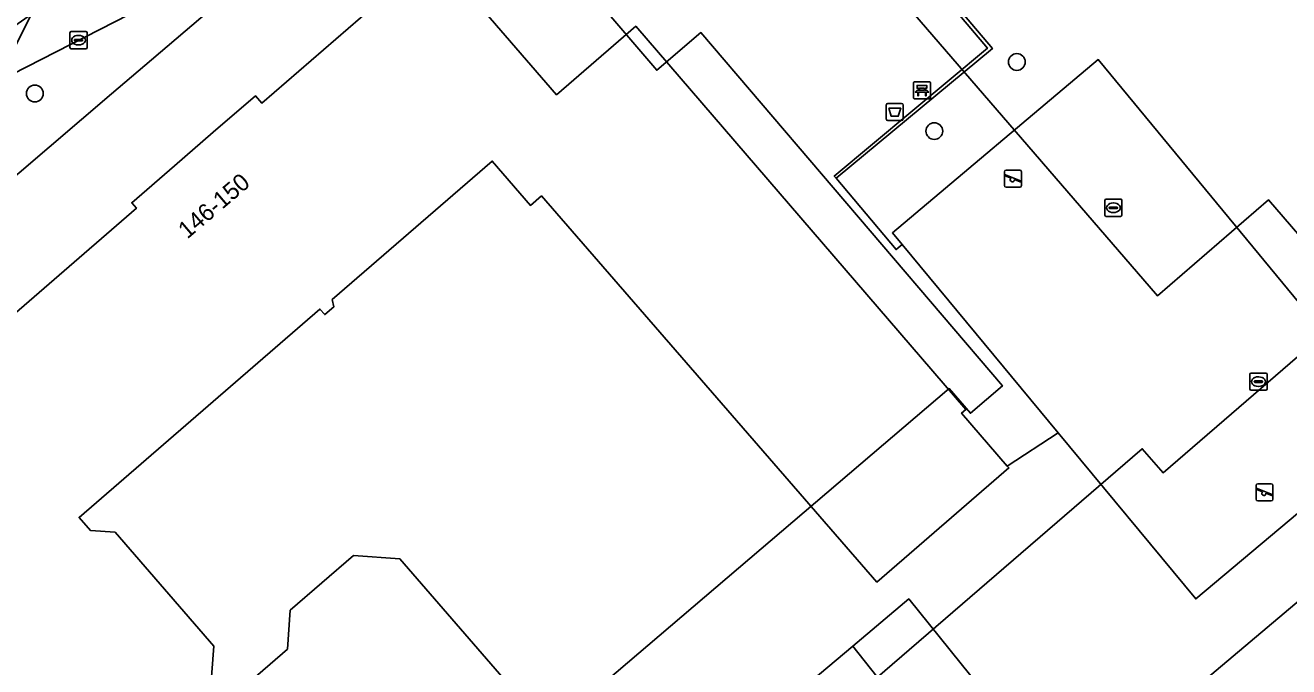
# Model space of a CAD drawing. Extents: x 162172 to 163187, y 382874 to 383685.
# Drawn here: x 162560 to 162633.7, y 383391.8 to 383429.2 of the extents above; entities that cross this region are included whole.
import ezdxf

# ---------------------------------------------------------------- set-up
doc = ezdxf.new("R2010")
doc.units = 0
for name, color, linetype in [('IMGEO_Afvalbak', 7, 'Continuous'), ('IMGEO_Bank', 7, 'Continuous'), ('IMGEO_Boom', 7, 'Continuous'), ('IMGEO_Erf', 7, 'Continuous'), ('IMGEO_Fietspad_gesloten', 7, 'Continuous'), ('IMGEO_Groenvoorziening', 7, 'Continuous'), ('IMGEO_Hek', 7, 'Continuous'), ('IMGEO_Kolk', 7, 'Continuous'), ('IMGEO_Muur', 7, 'Continuous'), ('IMGEO_Pand', 7, 'Continuous'), ('IMGEO_Pand_nummerreeks', 7, 'Continuous'), ('IMGEO_Pand_vergunning_verleend', 7, 'Continuous'), ('IMGEO_Parkeervlak_open', 7, 'Continuous'), ('IMGEO_Rijbaan_lokaal_gesloten', 7, 'Continuous'), ('IMGEO_Rijbaan_lokaal_open', 7, 'Continuous'), ('IMGEO_Speelvoorziening', 7, 'Continuous'), ('IMGEO_Terreindeel_gesloten', 7, 'Continuous'), ('IMGEO_Voetpad_open', 7, 'Continuous')]:
    doc.layers.add(name, color=color, linetype=linetype)

msp = doc.modelspace()

# ---------------------------------------------------------------- linework, layer by layer
at = {"layer": 'IMGEO_Afvalbak'}
for p, q in [((162610.314, 383424.681), (162611.104, 383424.681)), ((162611.104, 383424.681), (162610.314, 383424.681)), ((162610.214, 383423.781), (162610.214, 383424.581)), ((162610.214, 383424.581), (162610.214, 383423.781)), ((162611.204, 383424.581), (162611.204, 383423.781)), ((162611.204, 383423.781), (162611.204, 383424.581)), ((162611.104, 383423.681), (162610.314, 383423.681)), ((162610.314, 383423.681), (162611.104, 383423.681))]:
    msp.add_line(p, q, dxfattribs=at)
msp.add_lwpolyline([(162610.357, 383424.395), (162611.061, 383424.395), (162610.912, 383423.925), (162610.506, 383423.925), (162610.357, 383424.395)], dxfattribs=at)
for centre, start, end in [((162610.314, 383424.581), 90, 180), ((162610.314, 383424.581), 90, 180), ((162611.104, 383424.581), 0, 90), ((162611.104, 383424.581), 360, 90), ((162610.314, 383423.781), 180, 270), ((162610.314, 383423.781), 180, 270), ((162611.104, 383423.781), 270, 0), ((162611.104, 383423.781), 270, 0)]:
    msp.add_arc(centre, 0.1, start, end, dxfattribs=at)
at = {"layer": 'IMGEO_Bank'}
for p, q in [((162611.795, 383425.019), (162611.795, 383425.86)), ((162611.795, 383425.86), (162611.795, 383425.019)), ((162611.87, 383425.944), (162612.711, 383425.944)), ((162612.711, 383425.944), (162611.87, 383425.944)), ((162612.104, 383425.45), (162612.104, 383425.556)), ((162612.148, 383425.556), (162612.148, 383425.45)), ((162612.436, 383425.562), (162612.154, 383425.562)), ((162612.154, 383425.444), (162612.436, 383425.444)), ((162612.442, 383425.45), (162612.442, 383425.556)), ((162612.486, 383425.556), (162612.486, 383425.45)), ((162612.795, 383425.869), (162612.795, 383425.028)), ((162612.795, 383425.028), (162612.795, 383425.869)), ((162612.72, 383424.944), (162611.879, 383424.944)), ((162611.879, 383424.944), (162612.72, 383424.944)), ((162612.492, 383425.342), (162612.099, 383425.342))]:
    msp.add_line(p, q, dxfattribs=at)
for points in [[(162612.042, 383425.342), (162611.9, 383425.342), (162612.012, 383425.444), (162612.098, 383425.444)], [(162612.098, 383425.562), (162612.012, 383425.562), (162612.012, 383425.723), (162612.575, 383425.723), (162612.575, 383425.562), (162612.492, 383425.562)], [(162612.492, 383425.444), (162612.575, 383425.444), (162612.687, 383425.342), (162612.548, 383425.342)], [(162612.092, 383425.335), (162612.092, 383425.128), (162612.049, 383425.128), (162612.049, 383425.335)], [(162612.542, 383425.335), (162612.542, 383425.128), (162612.498, 383425.128), (162612.498, 383425.335)]]:
    msp.add_lwpolyline(points, dxfattribs=at)
for centre, radius, start, end in [((162611.873, 383425.866), 0.0779, 92.4484, 184.28452), ((162611.873, 383425.866), 0.0779, 92.4484, 184.28452), ((162612.097, 383425.555), 0.00671, 2.89567, 87.10433), ((162612.097, 383425.451), 0.00671, 272.89567, 357.10433), ((162612.154, 383425.555), 0.00671, 92.89567, 177.10433), ((162612.154, 383425.451), 0.00671, 182.89567, 267.10433), ((162612.436, 383425.555), 0.00671, 2.89567, 87.10433), ((162612.436, 383425.451), 0.00671, 272.89567, 357.10433), ((162612.493, 383425.555), 0.00671, 92.89567, 177.10433), ((162612.493, 383425.451), 0.00671, 182.89567, 267.10433), ((162612.717, 383425.866), 0.0779, 2.4484, 94.28452), ((162612.717, 383425.866), 0.0779, 2.4484, 94.28452), ((162611.873, 383425.022), 0.0779, 182.4484, 274.28452), ((162611.873, 383425.022), 0.0779, 182.4484, 274.28452), ((162612.042, 383425.335), 0.00671, 2.89567, 87.10433), ((162612.099, 383425.335), 0.00671, 92.89567, 177.10433), ((162612.491, 383425.335), 0.00671, 2.89567, 87.10433), ((162612.548, 383425.335), 0.00671, 92.89567, 177.10433), ((162612.717, 383425.022), 0.0779, 272.4484, 4.28452), ((162612.717, 383425.022), 0.0779, 272.4484, 4.28452)]:
    msp.add_arc(centre, radius, start, end, dxfattribs=at)
at = {"layer": 'IMGEO_Boom'}
for centre in [(162617.822, 383427.095), (162560.596, 383425.254), (162613.013, 383423.066)]:
    msp.add_circle(centre, 0.489, dxfattribs=at)
at = {"layer": 'IMGEO_Erf'}
for points in [[(162596.138, 383451.763), (162616.404, 383427.879), (162607.288, 383420.314), (162610.782, 383416.159), (162611.135, 383416.447), (162610.574, 383417.124), (162622.57, 383427.234), (162640.23, 383405.844), (162628.253, 383395.788), (162620.223, 383405.479), (162617.266, 383403.538), (162617.36, 383403.43), (162609.664, 383396.767), (162590.117, 383419.288), (162589.479, 383418.736), (162587.247, 383421.314), (162577.927, 383413.245), (162578.01, 383412.814), (162577.488, 383412.362), (162577.207, 383412.687), (162563.178, 383400.543), (162563.838, 383399.781), (162565.274, 383399.678), (162571.023, 383393.038), (162570.82, 383390.218)], [(162620.769, 383384.316), (162642.074, 383402.265)], [(162572.149, 383390.123), (162575.314, 383392.863), (162575.476, 383395.124), (162579.165, 383398.318), (162581.875, 383398.123), (162594.112, 383383.992)], [(162603.302, 383388.849), (162608.27, 383393.04), (162611.524, 383395.786), (162618.111, 383387.614)]]:
    msp.add_lwpolyline(points, dxfattribs=at)
at = {"layer": 'IMGEO_Fietspad_gesloten'}
msp.add_lwpolyline([(162560.399, 383429.887), (162558.403, 383425.945), (162567.8, 383430.751)], dxfattribs=at)
at = {"layer": 'IMGEO_Groenvoorziening'}
msp.add_lwpolyline([(162552.395, 383414.415), (162556.323, 383409.744), (162566.514, 383418.568), (162566.243, 383418.882), (162568.73, 383421.035), (162570.997, 383422.998), (162573.45, 383425.122), (162573.816, 383424.699), (162583.879, 383433.412), (162579.936, 383437.929), (162567.388, 383427.216), (162565.072, 383425.239)], close=True, dxfattribs=at)
at = {"layer": 'IMGEO_Hek'}
for points in [[(162611.135, 383416.447), (162610.574, 383417.124), (162622.57, 383427.234), (162640.23, 383405.844), (162628.253, 383395.788)], [(162620.223, 383405.479), (162611.135, 383416.447)], [(162617.266, 383403.538), (162620.223, 383405.479)], [(162628.253, 383395.788), (162620.223, 383405.479)]]:
    msp.add_lwpolyline(points, dxfattribs=at)
at = {"layer": 'IMGEO_Kolk'}
for p, q in [((162562.642, 383427.941), (162562.642, 383428.793)), ((162562.717, 383428.867), (162563.569, 383428.867)), ((162562.901, 383428.361), (162562.901, 383428.373)), ((162562.944, 383428.41), (162563.342, 383428.41)), ((162563.13, 383428.647), (162563.155, 383428.647)), ((162563.385, 383428.373), (162563.385, 383428.361)), ((162563.643, 383428.793), (162563.643, 383427.941)), ((162563.569, 383427.867), (162562.717, 383427.867)), ((162563.339, 383428.324), (162562.941, 383428.324)), ((162563.153, 383428.087), (162563.128, 383428.087)), ((162622.95, 383418.167), (162622.95, 383419.019)), ((162623.025, 383419.093), (162623.877, 383419.093)), ((162623.438, 383418.873), (162623.463, 383418.873)), ((162623.951, 383419.019), (162623.951, 383418.167)), ((162623.877, 383418.093), (162623.025, 383418.093)), ((162623.209, 383418.587), (162623.209, 383418.599)), ((162623.647, 383418.55), (162623.249, 383418.55)), ((162623.252, 383418.636), (162623.65, 383418.636)), ((162623.461, 383418.313), (162623.436, 383418.313)), ((162623.693, 383418.599), (162623.693, 383418.587)), ((162631.404, 383408.031), (162631.404, 383408.883)), ((162631.479, 383408.957), (162632.331, 383408.957)), ((162631.663, 383408.451), (162631.663, 383408.463)), ((162631.706, 383408.5), (162632.104, 383408.5)), ((162631.892, 383408.737), (162631.917, 383408.737)), ((162632.147, 383408.463), (162632.147, 383408.451)), ((162632.405, 383408.883), (162632.405, 383408.031)), ((162632.331, 383407.957), (162631.479, 383407.957)), ((162632.101, 383408.414), (162631.703, 383408.414)), ((162631.915, 383408.177), (162631.89, 383408.177))]:
    msp.add_line(p, q, dxfattribs=at)
for points in [[(162562.642, 383427.941), (162562.642, 383428.793)], [(162562.717, 383428.867), (162563.569, 383428.867)], [(162563.643, 383428.793), (162563.643, 383427.941)], [(162563.569, 383427.867), (162562.717, 383427.867)], [(162622.95, 383418.167), (162622.95, 383419.019)], [(162623.025, 383419.093), (162623.877, 383419.093)], [(162623.951, 383419.019), (162623.951, 383418.167)], [(162623.877, 383418.093), (162623.025, 383418.093)], [(162631.404, 383408.031), (162631.404, 383408.883)], [(162631.479, 383408.957), (162632.331, 383408.957)], [(162632.405, 383408.883), (162632.405, 383408.031)], [(162632.331, 383407.957), (162631.479, 383407.957)]]:
    msp.add_lwpolyline(points, dxfattribs=at)
for centre, radius, start, end in [((162562.719, 383428.791), 0.0765, 91.55205, 178.44795), ((162562.719, 383428.791), 0.0765, 91.55205, 178.44795), ((162562.941, 383428.37), 0.0403, 85.87752, 175.75265), ((162562.938, 383428.36), 0.0366, 178.93798, 274.71019), ((162563.342, 383428.367), 0.043, 264.86636, 352.45326), ((162563.346, 383428.372), 0.0386, 1.73085, 96.63898), ((162563.567, 383428.791), 0.0765, 1.55205, 88.44795), ((162563.567, 383428.791), 0.0765, 1.55205, 88.44795), ((162562.719, 383427.943), 0.0765, 181.55205, 268.44795), ((162562.719, 383427.943), 0.0765, 181.55205, 268.44795), ((162563.567, 383427.943), 0.0765, 271.55205, 358.44795), ((162563.567, 383427.943), 0.0765, 271.55205, 358.44795), ((162623.027, 383419.017), 0.0765, 91.55205, 178.44795), ((162623.027, 383419.017), 0.0765, 91.55205, 178.44795), ((162623.875, 383419.017), 0.0765, 1.55205, 88.44795), ((162623.875, 383419.017), 0.0765, 1.55205, 88.44795), ((162623.027, 383418.169), 0.0765, 181.55205, 268.44795), ((162623.027, 383418.169), 0.0765, 181.55205, 268.44795), ((162623.249, 383418.596), 0.0403, 85.87752, 175.75265), ((162623.246, 383418.586), 0.0366, 178.93798, 274.71019), ((162623.65, 383418.593), 0.043, 264.86636, 352.45326), ((162623.654, 383418.598), 0.0386, 1.73085, 96.63898), ((162623.875, 383418.169), 0.0765, 271.55205, 358.44795), ((162623.875, 383418.169), 0.0765, 271.55205, 358.44795), ((162631.481, 383408.881), 0.0765, 91.55205, 178.44795), ((162631.481, 383408.881), 0.0765, 91.55205, 178.44795), ((162631.703, 383408.46), 0.0403, 85.87752, 175.75265), ((162632.108, 383408.462), 0.0386, 1.73085, 96.63898), ((162632.329, 383408.881), 0.0765, 1.55205, 88.44795), ((162632.329, 383408.881), 0.0765, 1.55205, 88.44795), ((162631.481, 383408.033), 0.0765, 181.55205, 268.44795), ((162631.481, 383408.033), 0.0765, 181.55205, 268.44795), ((162631.7, 383408.45), 0.0366, 178.93798, 274.71019), ((162632.104, 383408.457), 0.043, 264.86636, 352.45326), ((162632.329, 383408.033), 0.0765, 271.55205, 358.44795), ((162632.329, 383408.033), 0.0765, 271.55205, 358.44795)]:
    msp.add_arc(centre, radius, start, end, dxfattribs=at)
for centre, major_axis, ratio, start_param, end_param in [((162563.129, 383428.367), (-0.387, 0.002), 0.722429, 4.712389, 7.853982), ((162563.154, 383428.367), (-0.39, 0.002), 0.717154, 1.570796, 4.712389), ((162623.437, 383418.593), (-0.387, 0.002), 0.722429, 4.712389, 7.853982), ((162623.462, 383418.593), (-0.39, 0.002), 0.717154, 1.570796, 4.712389), ((162631.891, 383408.457), (-0.387, 0.002), 0.722429, 4.712389, 7.853982), ((162631.916, 383408.457), (-0.39, 0.002), 0.717154, 1.570796, 4.712389)]:
    msp.add_ellipse(centre, major_axis=major_axis, ratio=ratio, start_param=start_param, end_param=end_param, dxfattribs=at)
at = {"layer": 'IMGEO_Muur'}
msp.add_lwpolyline([(162596.004, 383451.649), (162616.112, 383427.895), (162607.178, 383420.445), (162607.288, 383420.314), (162616.404, 383427.879), (162596.138, 383451.763)], close=True, dxfattribs=at)
at = {"layer": 'IMGEO_Pand'}
for points in [[(162570.82, 383390.218), (162571.023, 383393.038), (162565.274, 383399.678), (162563.838, 383399.781), (162563.178, 383400.543), (162577.207, 383412.687), (162577.488, 383412.362), (162578.01, 383412.814), (162577.927, 383413.245), (162587.247, 383421.314), (162589.479, 383418.736), (162590.117, 383419.288), (162609.664, 383396.767), (162617.36, 383403.43), (162617.266, 383403.538), (162614.599, 383406.619), (162614.841, 383406.828), (162595.611, 383429.18), (162591, 383425.186), (162583.879, 383433.412), (162573.816, 383424.699), (162573.45, 383425.122), (162570.997, 383422.998), (162568.73, 383421.035), (162566.243, 383418.882), (162566.514, 383418.568), (162556.323, 383409.744)], [(162594.112, 383383.992), (162581.875, 383398.123), (162579.165, 383398.318), (162575.476, 383395.124), (162575.314, 383392.863), (162572.149, 383390.123)]]:
    msp.add_lwpolyline(points, dxfattribs=at)
at = {"layer": 'IMGEO_Pand_vergunning_verleend'}
msp.add_lwpolyline([(162590.329, 383439.322), (162598.084, 383445.937), (162594.444, 383450.204), (162599.136, 383454.207), (162611.229, 383442.452), (162605.368, 383437.395), (162626.018, 383413.461), (162632.496, 383419.049), (162637.734, 383412.977), (162626.341, 383403.148), (162625.134, 383404.547), (162599.092, 383382.079), (162592.496, 383389.812), (162613.886, 383408.056), (162615.116, 383406.614), (162616.983, 383408.207), (162599.41, 383428.809), (162596.839, 383426.615), (162591.037, 383433.417), (162593.543, 383435.555)], close=True, dxfattribs=at)
at = {"layer": 'IMGEO_Parkeervlak_open'}
for points in [[(162617.266, 383403.538), (162620.223, 383405.479), (162611.135, 383416.447), (162610.782, 383416.159), (162607.288, 383420.314), (162607.178, 383420.445), (162616.112, 383427.895), (162596.004, 383451.649), (162589.352, 383445.969), (162587.439, 383444.336), (162582.374, 383440.011), (162579.936, 383437.929), (162583.879, 383433.412), (162591, 383425.186), (162595.611, 383429.18), (162614.841, 383406.828), (162614.599, 383406.619)], [(162643.158, 383401.027), (162642.074, 383402.265), (162620.769, 383384.316), (162618.111, 383387.614), (162611.524, 383395.786), (162608.27, 383393.04), (162617.405, 383381.482), (162619.242, 383379.303), (162622.604, 383382.138), (162623.703, 383380.833), (162643.694, 383397.868), (162651.152, 383404.224), (162651.495, 383404.516), (162649.554, 383406.289)]]:
    msp.add_lwpolyline(points, close=True, dxfattribs=at)
at = {"layer": 'IMGEO_Rijbaan_lokaal_gesloten'}
msp.add_lwpolyline([(162558.23, 383425.842), (162558.403, 383425.945), (162560.399, 383429.887), (162554.504, 383425.759), (162531.546, 383406.134), (162533.265, 383404.182), (162534.219, 383405.065), (162543.666, 383413.944), (162547.279, 383417.243), (162548.765, 383418.485), (162551.849, 383421.163)], dxfattribs=at)
at = {"layer": 'IMGEO_Rijbaan_lokaal_open'}
msp.add_lwpolyline([(162617.405, 383381.482), (162608.27, 383393.04), (162603.302, 383388.849)], dxfattribs=at)
at = {"layer": 'IMGEO_Speelvoorziening'}
for p, q in [((162617.1, 383419.89), (162617.1, 383420.69)), ((162617.1, 383420.69), (162617.1, 383419.89)), ((162617.483, 383420.318), (162617.144, 383420.455)), ((162617.169, 383420.515), (162618.045, 383420.162)), ((162617.2, 383420.79), (162617.99, 383420.79)), ((162617.99, 383420.79), (162617.2, 383420.79)), ((162618.09, 383420.69), (162618.09, 383419.89)), ((162618.09, 383419.89), (162618.09, 383420.69)), ((162617.99, 383419.79), (162617.2, 383419.79)), ((162617.2, 383419.79), (162617.99, 383419.79)), ((162618.021, 383420.102), (162617.681, 383420.239)), ((162631.761, 383401.604), (162631.761, 383402.404)), ((162631.761, 383402.404), (162631.761, 383401.604)), ((162632.144, 383402.032), (162631.805, 383402.169)), ((162631.83, 383402.229), (162632.706, 383401.876)), ((162631.861, 383402.504), (162632.651, 383402.504)), ((162632.651, 383402.504), (162631.861, 383402.504)), ((162632.682, 383401.816), (162632.342, 383401.953)), ((162632.751, 383402.404), (162632.751, 383401.604)), ((162632.751, 383401.604), (162632.751, 383402.404)), ((162632.651, 383401.504), (162631.861, 383401.504)), ((162631.861, 383401.504), (162632.651, 383401.504))]:
    msp.add_line(p, q, dxfattribs=at)
for centre, radius, start, end in [((162617.2, 383420.69), 0.1, 90, 180), ((162617.2, 383420.69), 0.1, 90, 180), ((162617.157, 383420.485), 0.0327, 68.07798, 248.07798), ((162617.562, 383420.228), 0.12, 130.99278, 5.16318), ((162617.99, 383420.69), 0.1, 0, 90), ((162617.99, 383420.69), 0.1, 360, 90), ((162617.2, 383419.89), 0.1, 180, 270), ((162617.2, 383419.89), 0.1, 180, 270), ((162617.99, 383419.89), 0.1, 270, 0), ((162617.99, 383419.89), 0.1, 270, 0), ((162618.033, 383420.132), 0.0327, 248.07798, 68.07798), ((162631.861, 383402.404), 0.1, 90, 180), ((162631.861, 383402.404), 0.1, 90, 180), ((162631.818, 383402.199), 0.0327, 68.07798, 248.07798), ((162632.223, 383401.942), 0.12, 130.99278, 5.16318), ((162632.651, 383402.404), 0.1, 0, 90), ((162632.651, 383402.404), 0.1, 360, 90), ((162632.694, 383401.846), 0.0327, 248.07798, 68.07798), ((162631.861, 383401.604), 0.1, 180, 270), ((162631.861, 383401.604), 0.1, 180, 270), ((162632.651, 383401.604), 0.1, 270, 0), ((162632.651, 383401.604), 0.1, 270, 0)]:
    msp.add_arc(centre, radius, start, end, dxfattribs=at)
at = {"layer": 'IMGEO_Terreindeel_gesloten'}
msp.add_lwpolyline([(162622.57, 383427.234), (162610.574, 383417.124), (162611.135, 383416.447), (162620.223, 383405.479), (162628.253, 383395.788), (162640.23, 383405.844)], close=True, dxfattribs=at)
at = {"layer": 'IMGEO_Voetpad_open'}
for points in [[(162528.583, 383392.222), (162529.74, 383393.652), (162529.793, 383395.041), (162534.559, 383399.04), (162538.848, 383402.638), (162538.745, 383402.761), (162542.159, 383405.676), (162552.395, 383414.415), (162565.072, 383425.239), (162567.388, 383427.216), (162579.936, 383437.929), (162582.374, 383440.011), (162587.439, 383444.336), (162589.352, 383445.969), (162596.004, 383451.649)], [(162567.8, 383430.751), (162558.403, 383425.945), (162558.23, 383425.842)]]:
    msp.add_lwpolyline(points, dxfattribs=at)

# ---------------------------------------------------------------- texts
at = {"layer": 'IMGEO_Pand_nummerreeks'}
msp.add_text('146-150', height=1, rotation=40.47374, dxfattribs=at).set_placement((162569.481, 383416.74))

doc.saveas('drawing.dxf')
